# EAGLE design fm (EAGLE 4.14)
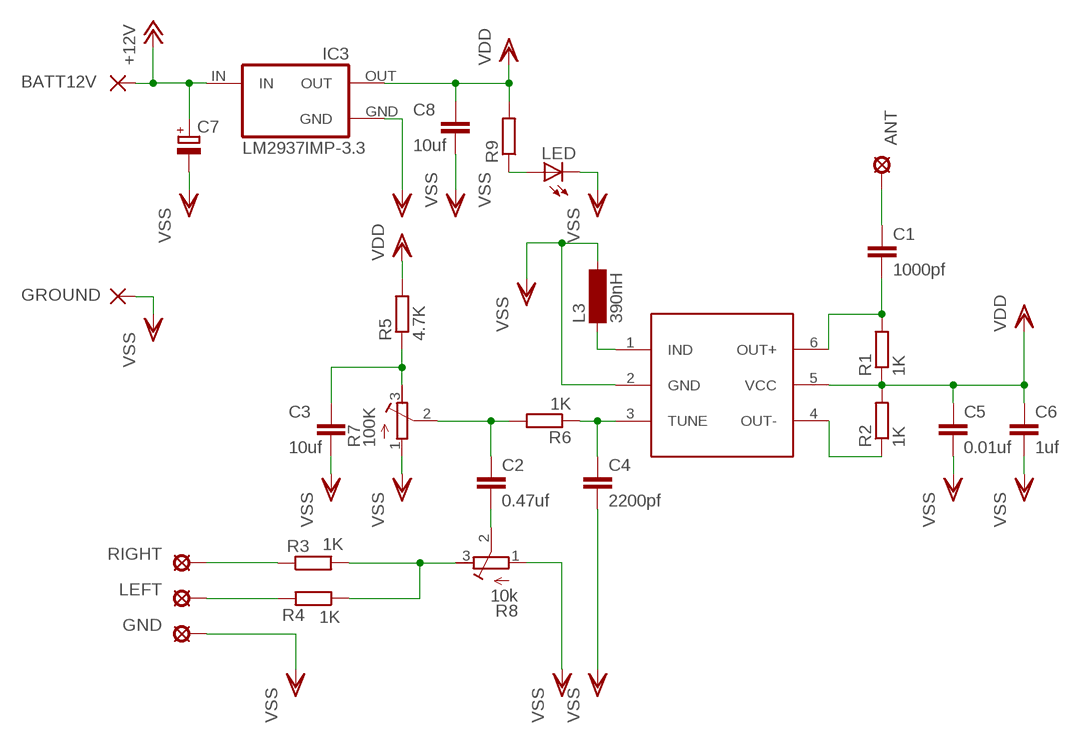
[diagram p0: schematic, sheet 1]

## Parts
ANT  SE14  [SE14]
BATT12V  SMD5  [SMD5]
C1  1000pf  C-EUC0603  [C0603]
C2  0.47uf  C-EUC0805  [C0805]
C3  10uf  C-EUC0805  [C0805]
C4  2200pf  C-EUC0603  [C0603]
C5  0.01uf  C-EUC0805  [C0805]
C6  1uf  C-EUC0805  [C0805]
C7  CPOL-EU153CLV-0810  [153CLV-0810]
C8  10uf  C-EUC0805  [C0805]
GND  SE14  [SE14]
GROUND  SMD5  [SMD5]
IC1  MAX260X  [SOT23-6]
IC3  LM2937IMP-3.3  [SOT223]
L3  390nH  SM-NE29  [SM-NE29]
LED  LEDSIDELED  [OSRAM-SIDELED]
LEFT  SE14  [SE14]
R1  1K  R-EU_M0805  [M0805]
R2  1K  R-EU_M0805  [M0805]
R3  1K  R-EU_M0805  [M0805]
R4  1K  R-EU_M0805  [M0805]
R5  4.7K  R-EU_M0805  [M0805]
R6  1K  R-EU_M0805  [M0805]
R7  100K  R-TRIMM3103  [RTRIM3103]
R8  10k  R-TRIMM3103  [RTRIM3103]
R9  R-EU_M0805  [M0805]
RIGHT  SE14  [SE14]

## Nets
+12V: BATT12V.1(P) C7.+ IC3.IN
N$1: R3.2 R4.1 R8.3(A)
N$2: IC1.4(OUT-) R2.1
N$3: C1.2 IC1.6(OUT+) R1.2
N$4: R3.1 RIGHT.MP
N$5: LEFT.MP R4.2
N$6: C3.1 R5.1 R7.3(A)
N$7: ANT.MP C1.1
N$8: C4.1 IC1.3(TUNE) R6.1
N$9: C2.2 R8.2(S)
N$10: C2.1 R6.2 R7.2(S)
N$12: IC1.1(IND) L3.1
N$15: LED.A R9.1
VDD: C5.1 C6.1 C8.1 IC1.5(VCC) IC3.OUT R1.1 R2.2 R5.2 R9.2
VSS: C3.2 C4.2 C5.2 C6.2 C7.- C8.2 GND.MP GROUND.1(P) IC1.2(GND) IC3.GND L3.2 LED.C R7.1(E) R8.1(E)

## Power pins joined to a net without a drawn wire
GND: IC3.GND@(GND)

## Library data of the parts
ANT GND LEFT RIGHT = solpad:SE14: SOLDER PAD
BATT12V GROUND = wirepad:SMD5: SMD PAD
C1-C6 C8 = rcl:C-EU: CAPACITOR, European symbol
C7 = rcl:CPOL-EU: POLARIZED CAPACITOR, European symbol
IC1 = max260X:MAX260X
IC3 = lm2937:LM2937IMP-*: 400 and 500 mA Low Dropout Voltage Regulator NATIONAL SEMICONDUCTOR created by Peter.Hofmann@ph-tronic.de 10-2004 Rev.0
L3 = inductor-neosid:SM-NE29: INDUCTOR
LED = led:LED: LED
R1-R6 R9 = rcl:R-EU_: RESISTOR, European symbol
R7 R8 = rcl:R-TRIMM: Trimm resistor

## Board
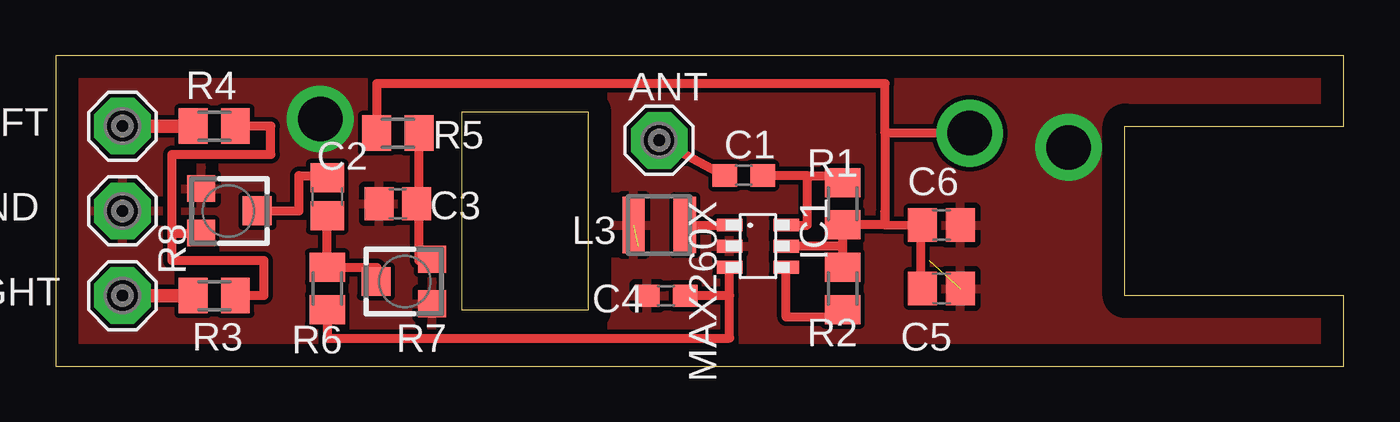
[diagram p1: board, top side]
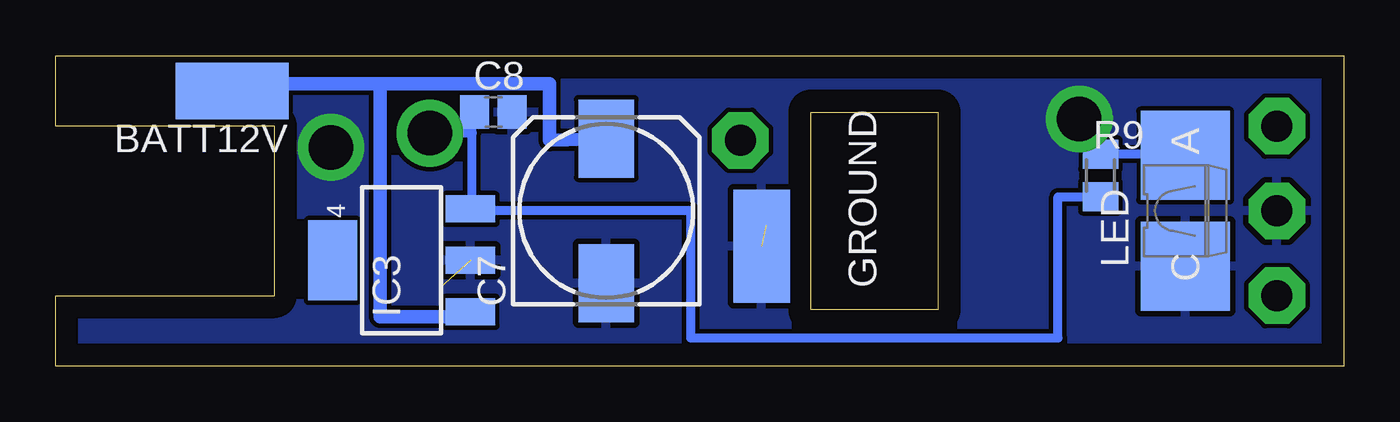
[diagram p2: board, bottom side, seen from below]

Size 57.94 x 13.96 mm. Coordinates in mm from the lower left corner, seen from the top.
Outline: 57.94,13.96 57.94,10.79 48.09,10.79 48.09,3.17 57.94,3.17 57.93,0 0,0 0,13.96 57.94,13.96
Outline: 57.94,13.96 17.45,13.96
Outline: 18.25,2.54 23.96,2.54 23.96,11.43 18.25,11.43 18.25,2.54
Copper layers (1*16): Top 0.035mm / dielectric 1.5mm / Bottom 0.035mm
Design rules "default": minimum track width 10mil, minimum drill 24mil, track to track 8mil, track to pad 8mil, pad to pad 8mil, via to via 8mil, smd to smd 8mil, copper to edge 40mil, drill to drill 8mil, minimum pad ring 10mil, minimum via ring 8mil, stop-mask expansion 4mil, vias tented up to drill 0mil, thermal gap 10mil

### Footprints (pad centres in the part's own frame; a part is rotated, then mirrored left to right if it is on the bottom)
SE14 = drill 1.397 pad 2.54 octagon: MP 0,0
SMD5 = smd 2.54 x 5.08: 1 0,0
C0603 = smd 1.1 x 1: 1 -0.85,0; 2 0.85,0
C0805 = smd 1.3 x 1.5: 1 -0.85,0; 2 0.85,0
153CLV-0810 = smd 3.5 x 2.5: + 3.25,0; - -3.25,0
SOT23-6 = smd 0.584 x 1.143: 1 -0.953,-1.27; 2 0,-1.27; 3 0.953,-1.27; 4 0.953,1.27; 5 0,1.27; 6 -0.953,1.27
SOT223 = smd 1.219 x 2.235: GND 0,-3.099; IN -2.311,-3.099; OUT 2.311,-3.099 | smd 3.6 x 2.2: GND@ 0,3.099
SM-NE29 = smd 1 x 2.54: 1 -1.15,0; 2 1.15,0
OSRAM-SIDELED = smd 4 x 4: A 0,2.5; C 0,-2.5
M0805 = smd 1.3 x 1.6: 1 -0.95,0; 2 0.95,0
RTRIM3103 = smd 1.2 x 1.25: 1 -1,-1.225; 3 1,-1.225 | smd 1.3 x 1.3: 2 0,1.3

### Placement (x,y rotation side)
ANT  27.14,10.16 0 top
BATT12V  50,12.38 90 bottom
C1  30.95,8.57 0 top
C2  12.22,7.62 90 top
C3  15.39,7.3 180 top
C4  27.46,3.17 180 top
C5  39.84,3.49 0 top
C6  39.84,6.34 0 top
C7  33.17,6.98 90 bottom
C8  38.25,11.43 0 bottom
GND  3.01,6.98 0 top
GROUND  26.19,5.39 0 bottom
IC1  31.58,5.39 270 top
IC3  42.38,4.76 90 bottom
L3  27.14,6.34 180 top
LED  7.14,6.98 0 bottom
LEFT  3.01,10.79 0 top
R1  35.39,7.3 90 top
R2  35.39,3.49 90 top
R3  7.14,3.17 0 top
R4  7.14,10.79 180 top
R5  15.39,10.47 180 top
R6  12.22,3.49 90 top
R7  15.71,3.8 90 top
R8  7.77,6.98 270 top
R9  10.95,8.57 270 bottom
RIGHT  3.01,3.17 0 top

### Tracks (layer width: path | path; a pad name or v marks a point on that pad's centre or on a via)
+12V
  Bottom 0.406: 39.2,2.22 IC3.IN
  Bottom 0.61: 39.52,2.54 39.52,2.45 IC3.IN | C7.+ 35.71,10.16 35.71,12.7 43.33,12.7 | 43.33,12.7 48.09,12.7 BATT12V.1 | 39.2,2.22 43.33,2.22 43.33,12.7
N$1  (1 unrouted)
  Top 0.406: R3.2 9.36,3.17 9.36,4.76 5.23,4.76 5.23,5.98 R8.3 | R4.1 9.68,10.79 9.68,9.52 5.23,9.52 5.23,6.03
N$2
  Top 0.406: IC1.4 32.85,2.22 35.39,2.22 R2.1
N$3
  Top 0.406: IC1.6 33.81,6.34 33.81,8.57 | R1.2 35.08,8.57 33.81,8.57 | 33.81,8.57 C1.2
N$4
  Top 0.61: RIGHT.MP R3.1
N$5
  Top 0.61: LEFT.MP R4.2
N$6
  Top 0.406: R7.3 16.34,4.76 16.34,7.3 | 16.34,7.3 C3.1 | 16.34,7.3 R5.1
N$7
  Top 0.406: ANT.MP C1.1
N$8
  Top 0.406: R6.1 12.22,1.27 30.31,1.27 30.31,3.17 | 30.31,3.17 IC1.3 | 30.31,3.17 C4.1
N$9
  Top 0.406: 9.68,6.98 R8.2 10.95,6.98 10.95,8.57 12.22,8.57 C2.2
N$10
  Top 0.406: C2.1 R6.2 14.44,4.44 14.44,3.8 R7.2
N$12
  Top 0.406: L3.1 IC1.1
N$15
  Bottom 0.406: R9.1 7.77,9.52 LED.A
VDD  (via drill 2 pad 2.18)
  Top 0.406: R5.2 14.44,12.7 37.3,12.7 37.3,10.47 | 35.39,5.39 R2.2 | 35.39,5.39 IC1.5 | 35.39,5.39 R1.1 37.3,6.35 | 37.3,6.35 38.89,6.34 | 38.89,6.34 C6.1 | C5.1 38.89,3.49 38.89,6.34 | 37.3,6.35 37.3,6.98 | 37.3,10.47 37.3,6.35 | v41.11,10.47 37.3,10.47
  Bottom 0.406: 39.2,6.98 IC3.OUT | 39.2,10.47 v41.11,10.47 | 39.2,6.98 39.2,10.47 | 39.2,6.98 29.36,6.98 29.36,1.27 12.85,1.27 12.85,7.62 10.63,7.62 R9.2 | C8.1 39.2,11.43 39.2,10.47
VSS  (via drill 2 pad 2.18)  (2 unrouted)
  other vias: 11.9,11.11 45.55,9.84
  pour Top: 0.47,13.33 58.25,13.33 58.25,11.43 47.46,11.43 47.46,2.54 58.25,2.54 58.25,0.63 0.47,0.63
  pour Bottom: 0.47,13.33 58.25,13.33 58.25,11.43 47.46,11.43 47.46,2.54 58.25,2.54 58.25,0.63 0.47,0.63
